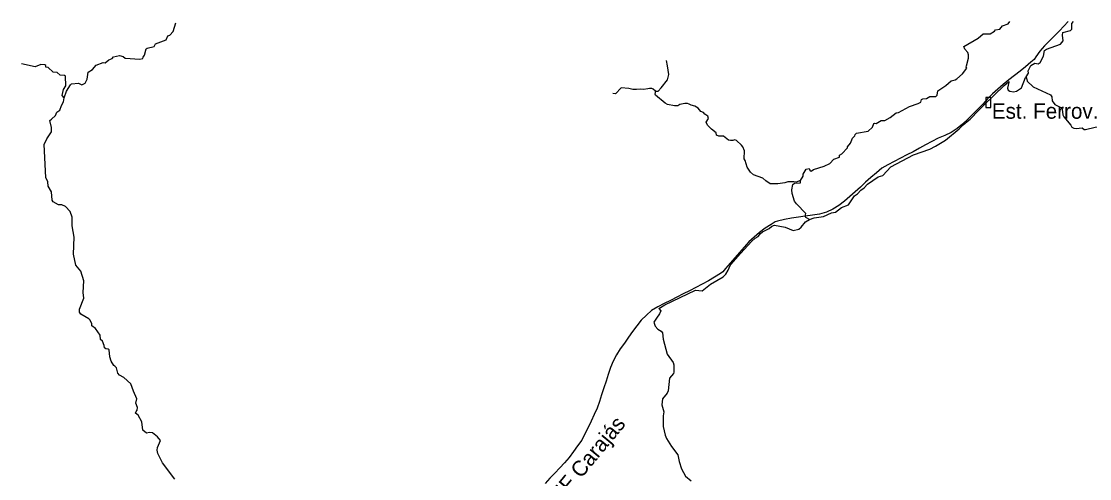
# Model space of a CAD drawing. Extents: x 332 to 501, y 9447 to 9559.
# Drawn here: x 333.47 to 359.78, y 9546.5 to 9557.76 of the extents above; entities that cross this region are included whole.
import ezdxf

# ---------------------------------------------------------------- set-up
doc = ezdxf.new("R2010")
doc.units = 0
for name, color, linetype in [('Level 19', 7, 'Continuous'), ('Level 22', 7, 'Continuous'), ('Level 28', 7, 'Continuous'), ('Level 31', 7, 'Continuous'), ('Level 4', 7, 'Continuous'), ('Level 5', 7, 'Continuous'), ('Level 6', 7, 'Continuous')]:
    doc.layers.add(name, color=color, linetype=linetype)

msp = doc.modelspace()

# ---------------------------------------------------------------- linework, layer by layer
at = {"layer": 'Level 22'}
for points in [[(359.2521, 9557.7639), (359.0383, 9557.5322)], [(359.0383, 9557.5322), (358.9143, 9557.4088)], [(358.7903, 9557.2853), (358.6662, 9557.1618)], [(358.9143, 9557.4088), (358.7903, 9557.2853)], [(358.5512, 9557.0309), (358.4517, 9556.887)], [(358.6662, 9557.1618), (358.5512, 9557.0309)], [(358.3324, 9556.761), (358.1983, 9556.6486)], [(358.4517, 9556.887), (358.4091, 9556.8253), (358.3324, 9556.761)], [(357.9247, 9556.4306), (357.7868, 9556.3229)], [(358.0642, 9556.5361), (357.9247, 9556.4306)], [(358.1983, 9556.6486), (358.0642, 9556.5361)], [(357.6506, 9556.213), (357.5185, 9556.0983)], [(357.7868, 9556.3229), (357.6506, 9556.213)], [(357.3864, 9555.9835), (357.2677, 9555.855)], [(357.5185, 9556.0983), (357.3864, 9555.9835)], [(357.1499, 9555.7256), (357.027, 9555.6011)], [(357.2677, 9555.855), (357.1499, 9555.7256)], [(356.7764, 9555.3567), (356.6512, 9555.2345)], [(356.9017, 9555.4789), (356.7764, 9555.3567)], [(357.027, 9555.6011), (356.9017, 9555.4789)], [(356.5153, 9555.1252), (356.3694, 9555.0291)], [(356.6512, 9555.2345), (356.5153, 9555.1252)], [(356.0504, 9554.885), (355.8943, 9554.8063)], [(356.2099, 9554.9571), (356.0504, 9554.885)], [(356.3694, 9555.0291), (356.2099, 9554.9571)], [(355.5868, 9554.6391), (355.4331, 9554.5554)], [(355.7405, 9554.7227), (355.5868, 9554.6391)], [(355.8943, 9554.8063), (355.7405, 9554.7227)], [(354.9676, 9554.3127), (354.8122, 9554.2321)], [(355.123, 9554.3933), (354.9676, 9554.3127)], [(355.2783, 9554.4739), (355.123, 9554.3933)], [(355.4331, 9554.5554), (355.2783, 9554.4739)], [(354.6602, 9554.1467), (354.5276, 9554.0325)], [(354.8122, 9554.2321), (354.6602, 9554.1467)], [(354.2635, 9553.8029), (354.134, 9553.6851)], [(354.3951, 9553.9181), (354.2635, 9553.8029)], [(354.5276, 9554.0325), (354.3951, 9553.9181)], [(354.0046, 9553.5673), (353.8752, 9553.4495)], [(354.134, 9553.6851), (354.0046, 9553.5673)], [(353.7388, 9553.3399), (353.6022, 9553.2305)], [(353.8752, 9553.4495), (353.7388, 9553.3399)], [(352.9554, 9552.9917), (352.7702, 9552.9656)], [(353.1285, 9553.0174), (352.9554, 9552.9917)], [(353.2968, 9553.0641), (353.1285, 9553.0174)], [(353.4553, 9553.1367), (353.2968, 9553.0641)], [(353.6022, 9553.2305), (353.4553, 9553.1367)], [(351.9402, 9552.7625), (351.7926, 9552.6684)], [(352.0947, 9552.8413), (352.0369, 9552.8241), (351.9402, 9552.7625)], [(352.263, 9552.8889), (352.0947, 9552.8413)], [(352.4361, 9552.9146), (352.263, 9552.8889)], [(352.6092, 9552.9403), (352.4361, 9552.9146)], [(352.7702, 9552.9656), (352.6092, 9552.9403)], [(351.6529, 9552.5638), (351.5201, 9552.4499)], [(351.7926, 9552.6684), (351.6529, 9552.5638)], [(351.2691, 9552.2072), (351.1551, 9552.0745)], [(351.3872, 9552.3359), (351.2691, 9552.2072)], [(351.5201, 9552.4499), (351.3872, 9552.3359)], [(351.0412, 9551.9417), (350.9272, 9551.8089)], [(351.1551, 9552.0745), (351.0412, 9551.9417)], [(350.8132, 9551.6761), (350.7446, 9551.5962), (350.6857, 9551.5589)], [(350.9272, 9551.8089), (350.8132, 9551.6761)], [(350.5378, 9551.4654), (350.3899, 9551.3719)], [(350.6857, 9551.5589), (350.5378, 9551.4654)], [(350.0787, 9551.2118), (349.9227, 9551.1325)], [(350.2347, 9551.2911), (350.0787, 9551.2118)], [(350.3899, 9551.3719), (350.2347, 9551.2911)], [(349.4548, 9550.8947), (349.2998, 9550.8133)], [(349.6108, 9550.974), (349.4548, 9550.8947)], [(349.7667, 9551.0532), (349.6108, 9550.974)], [(349.9227, 9551.1325), (349.7667, 9551.0532)], [(348.9922, 9550.6472), (348.8641, 9550.528)], [(349.145, 9550.7316), (348.9922, 9550.6472)], [(349.2998, 9550.8133), (349.145, 9550.7316)], [(348.7365, 9550.4083), (348.6302, 9550.2693)], [(348.8641, 9550.528), (348.7365, 9550.4083)], [(348.5238, 9550.1303), (348.4224, 9549.9878)], [(348.6302, 9550.2693), (348.5238, 9550.1303)], [(348.3226, 9549.8441), (348.2228, 9549.7003)], [(348.4224, 9549.9878), (348.3226, 9549.8441)], [(348.2228, 9549.7003), (348.1296, 9549.5525)], [(348.0493, 9549.397), (347.9791, 9549.2374)], [(348.1296, 9549.5525), (348.0493, 9549.397)], [(347.9266, 9549.0704), (347.874, 9548.9036)], [(347.9791, 9549.2374), (347.9266, 9549.0704)], [(347.874, 9548.9036), (347.8181, 9548.7377)], [(347.7622, 9548.5719), (347.7063, 9548.4061)], [(347.8181, 9548.7377), (347.7622, 9548.5719)], [(347.7063, 9548.4061), (347.6504, 9548.2402)], [(347.5796, 9548.0805), (347.5033, 9547.923)], [(347.6504, 9548.2402), (347.5796, 9548.0805)], [(347.4271, 9547.7654), (347.3509, 9547.6079)], [(347.5033, 9547.923), (347.4271, 9547.7654)], [(347.3509, 9547.6079), (347.2747, 9547.4504)], [(347.1708, 9547.3096), (347.0664, 9547.1692)], [(347.2747, 9547.4504), (347.1708, 9547.3096)], [(346.962, 9547.0287), (346.8506, 9546.8942)], [(347.0664, 9547.1692), (346.962, 9547.0287)], [(346.7301, 9546.7672), (346.6097, 9546.6403)], [(346.8506, 9546.8942), (346.7301, 9546.7672)], [(346.4892, 9546.5133), (346.3688, 9546.3863)], [(346.6097, 9546.6403), (346.4892, 9546.5133)]]:
    msp.add_lwpolyline(points, dxfattribs=at)
at = {"layer": 'Level 28'}
msp.add_lwpolyline([(357.2197, 9555.6407), (357.3447, 9555.6407), (357.3447, 9555.8907), (357.2197, 9555.8907)], close=True, dxfattribs=at)
at = {"layer": 'Level 4'}
for points in [[(334.5321, 9555.8808), (334.4776, 9555.9398), (334.5094, 9556.0852), (334.5684, 9556.176), (334.5593, 9556.4167), (334.5366, 9556.4349), (334.4277, 9556.4394), (334.355, 9556.503), (334.2597, 9556.5121), (334.1372, 9556.6302), (334.0782, 9556.6347), (334.0782, 9556.6802), (334.0509, 9556.6938), (333.9556, 9556.7029), (333.8149, 9556.6484), (333.4743, 9556.7219)], [(334.0796, 9553.9164), (334.0388, 9554.7339), (334.0974, 9554.8757), (334.22, 9555.0438), (334.22, 9555.1483), (334.1746, 9555.3254), (334.22, 9555.3526), (334.3108, 9555.448), (334.3516, 9555.5298), (334.4242, 9555.5797), (334.4605, 9555.6933), (334.5105, 9555.7796), (334.5321, 9555.8808)], [(334.722, 9552.9389), (334.6727, 9553.0825), (334.5638, 9553.2052), (334.4685, 9553.246), (334.3883, 9553.2488), (334.2612, 9553.3214), (334.2294, 9553.3623), (334.2203, 9553.5667), (334.1341, 9553.7029), (334.125, 9553.812), (334.0796, 9553.9164)], [(335.6395, 9549.6757), (335.6123, 9549.6939), (335.5533, 9549.6984), (335.5215, 9549.7257), (335.517, 9549.7847), (335.4716, 9549.8892), (335.4262, 9549.9301), (335.4171, 9550.0391), (335.2991, 9550.198), (335.2129, 9550.2662), (335.2129, 9550.3161), (335.1675, 9550.4069), (335.1357, 9550.4433), (334.9405, 9550.5523), (334.9087, 9550.6068), (334.9042, 9550.6749), (335.0086, 9550.9474), (334.995, 9551.0882), (335.0086, 9551.3789), (334.9405, 9551.613), (334.818, 9551.7629), (334.759, 9552.0354), (334.7726, 9552.4487), (334.7272, 9552.7303), (334.722, 9552.9389)], [(337.2496, 9546.4905), (336.9455, 9546.8901), (336.8366, 9547.1218), (336.8184, 9547.2035), (336.8275, 9547.2716), (336.9001, 9547.4442), (336.8275, 9547.5371), (336.7004, 9547.6324), (336.6323, 9547.6415), (336.5551, 9547.6279), (336.4689, 9547.696), (336.4371, 9547.905), (336.3471, 9548.0643), (336.2873, 9548.1139), (336.3009, 9548.1593), (336.3282, 9548.1865), (336.3327, 9548.2547), (336.2964, 9548.3591), (336.3146, 9548.4727), (336.2329, 9548.6543), (336.1738, 9548.8385), (336.0014, 9548.993), (335.8879, 9549.052), (335.8516, 9549.102), (335.8153, 9549.2291), (335.7789, 9549.2745), (335.7472, 9549.2882), (335.6849, 9549.3941), (335.6532, 9549.5077), (335.6395, 9549.6757)]]:
    msp.add_lwpolyline(points, dxfattribs=at)
at = {"layer": 'Level 5'}
for points in [[(334.5321, 9555.8808), (334.5876, 9556.043), (334.683, 9556.2019), (334.7102, 9556.2292), (334.8781, 9556.2383), (334.9644, 9556.1974), (335.0461, 9556.2383), (335.096, 9556.3382), (335.1187, 9556.5153), (335.2231, 9556.5789), (335.3139, 9556.6879), (335.4909, 9556.7515), (335.5401, 9556.7432), (335.6263, 9556.8159), (335.708, 9556.8477), (335.7444, 9556.8931), (335.8941, 9556.9204), (335.9804, 9556.8977), (336.0303, 9556.8613), (336.3935, 9556.8341), (336.4661, 9556.8477), (336.4706, 9556.884), (336.5069, 9556.9295), (336.5478, 9557.0839), (336.5705, 9557.1066), (336.743, 9557.1475), (336.7793, 9557.211), (337.038, 9557.3064), (337.0789, 9557.4063), (337.1333, 9557.4245), (337.215, 9557.5108), (337.2763, 9557.7273)], [(356.7493, 9556.6676), (356.7964, 9556.8559), (356.7964, 9556.9416), (356.7836, 9556.9972), (356.7065, 9557.0828), (356.6851, 9557.147), (357.0318, 9557.3483), (357.156, 9557.4597), (357.3315, 9557.4554), (357.4342, 9557.5196), (357.4642, 9557.5582), (357.5669, 9557.5753), (357.6312, 9557.6567), (357.7767, 9557.6995), (357.8101, 9557.7616)], [(358.2122, 9556.4015), (358.2717, 9556.4886), (358.2667, 9556.5476), (358.3307, 9556.6755), (358.429, 9556.7345), (358.5126, 9556.7148), (358.5569, 9556.7492), (358.6454, 9556.9066), (358.6651, 9557.0443), (358.7142, 9557.0836), (359.0585, 9557.2017), (359.1273, 9557.2846), (359.1076, 9557.4224), (359.1175, 9557.4913), (359.3043, 9557.5356), (359.3388, 9557.57), (359.3437, 9557.7127), (359.3777, 9557.7641)], [(355.0135, 9555.5139), (355.0685, 9555.5208), (355.3399, 9555.6651), (355.5592, 9555.7386), (355.6192, 9555.7729), (355.6406, 9555.8371), (355.6748, 9555.8542), (355.7604, 9555.8671), (355.8461, 9555.9141), (355.9916, 9555.9141), (356.0258, 9555.9441), (356.0387, 9556.0511), (356.2399, 9556.1838), (356.3683, 9556.3037), (356.4711, 9556.3208), (356.5053, 9556.3465), (356.6508, 9556.4749), (356.7579, 9556.6119)], [(356.7579, 9556.6119), (356.7365, 9556.6333), (356.7493, 9556.6676)], [(357.1753, 9555.7025), (357.6715, 9556.1889)], [(357.6715, 9556.1889), (357.778, 9556.278)], [(357.778, 9556.278), (357.7916, 9556.2827), (357.7928, 9556.2704), (357.7572, 9556.1167), (357.7768, 9556.0712), (357.8137, 9556.0454), (357.9072, 9556.0306), (357.9748, 9556.0442), (358.1026, 9556.1253), (358.1961, 9556.3823)], [(358.1961, 9556.3823), (358.2122, 9556.4015)], [(358.2122, 9556.4015), (358.2422, 9556.2956), (358.3848, 9556.148), (358.8126, 9555.9561), (358.847, 9555.902), (358.8568, 9555.8085), (358.9208, 9555.715), (359.0716, 9555.6432), (359.1011, 9555.6039), (359.1208, 9555.4612), (359.1405, 9555.4169), (359.3175, 9555.2053), (359.3372, 9555.161), (359.3913, 9555.1315), (359.4503, 9555.1266), (359.5929, 9555.1413), (359.6421, 9555.102), (359.6765, 9555.102), (359.9174, 9555.161), (360.0945, 9555.166), (360.1781, 9555.1069), (360.2027, 9555.0577), (360.2568, 9555.0331)], [(352.6618, 9553.8449), (352.5544, 9553.8035), (352.4945, 9553.8164), (352.3447, 9553.8121), (352.2762, 9553.7864), (352.1007, 9553.7607), (351.9123, 9553.765), (351.8096, 9553.8335), (351.7282, 9553.9021), (351.5014, 9553.9834), (351.4243, 9554.052), (351.343, 9554.1762), (351.2959, 9554.339), (351.2745, 9554.3818), (351.283, 9554.5745), (351.2402, 9554.6731), (351.206, 9554.7159), (351.0861, 9554.8273), (351.0433, 9554.8444), (350.9919, 9554.8316), (350.9363, 9554.8273), (350.8849, 9554.8358), (350.7651, 9554.9386), (350.6495, 9554.9344), (350.5895, 9554.9643), (350.5853, 9555.02), (350.4654, 9555.1057), (350.3712, 9555.2085), (350.3327, 9555.2813), (350.3969, 9555.3713), (350.3755, 9555.4296), (350.307, 9555.481), (350.2728, 9555.5238), (350.2043, 9555.541), (350.1401, 9555.6267), (350.0587, 9555.6781), (349.9688, 9555.6995), (349.9217, 9555.7252), (349.8746, 9555.738), (349.8147, 9555.738), (349.6863, 9555.7166), (349.6392, 9555.6866), (349.6221, 9555.6882), (349.5595, 9555.6866), (349.3883, 9555.7209), (349.3241, 9555.7466), (349.0886, 9555.9436), (349.0801, 9555.9736), (349.0929, 9556.0122), (349.0929, 9556.0464), (349.033, 9556.0978), (348.9945, 9556.115), (348.9431, 9556.115), (348.896, 9556.1021), (348.7933, 9556.0893), (348.729, 9556.0978), (348.6177, 9556.085), (348.5279, 9556.085), (348.4294, 9556.115), (348.241, 9556.1235), (348.1041, 9555.9822), (348.0356, 9555.9865)], [(357.051, 9555.5765), (357.1753, 9555.7025)], [(352.6619, 9553.8449), (352.7244, 9553.955), (352.7244, 9553.9996), (352.8001, 9554.1246), (352.8715, 9554.1424), (352.8893, 9554.0978), (352.9205, 9554.0755), (352.9785, 9554.1156), (353.246, 9554.2004), (353.3798, 9554.2673), (353.4765, 9554.3699), (353.6192, 9554.419), (353.6192, 9554.4725), (353.6788, 9554.5061), (353.8171, 9554.6493), (353.8154, 9554.6721), (353.891, 9554.7649), (353.9425, 9554.8885), (354.0009, 9554.9435), (354.0078, 9554.9779), (354.0422, 9555.0122), (354.3239, 9555.0569), (354.4304, 9555.1565), (354.4647, 9555.2458), (354.4888, 9555.2596), (354.5232, 9555.2493), (354.6468, 9555.3214), (354.7396, 9555.3249), (354.8667, 9555.397), (355.0135, 9555.5139)], [(356.8023, 9555.3302), (356.8347, 9555.3571)], [(356.8347, 9555.3571), (357.051, 9555.5765)], [(352.8846, 9552.8893), (352.992, 9552.9296), (353.2267, 9552.9631), (353.4223, 9553.047), (353.5173, 9553.0638), (353.6682, 9553.1812), (353.8414, 9553.2427), (353.9923, 9553.4646), (354.0649, 9553.5205), (354.1432, 9553.6099), (354.227, 9553.6659), (354.3108, 9553.7553), (354.5679, 9553.9343), (354.6852, 9553.9678), (354.8864, 9554.1859), (355.4432, 9554.4736), (355.84, 9554.619), (355.9853, 9554.6917), (356.2256, 9554.8427), (356.5665, 9555.1167), (356.6675, 9555.2178)], [(356.6675, 9555.2178), (356.8023, 9555.3302)], [(352.7702, 9552.9656), (352.7928, 9553.0305), (352.5594, 9553.2694), (352.5148, 9553.3363), (352.4568, 9553.5237), (352.4435, 9553.6174), (352.4702, 9553.7512), (352.5148, 9553.7825), (352.6575, 9553.7869), (352.6619, 9553.8449)], [(351.6731, 9552.5401), (351.726, 9552.5824), (351.8881, 9552.6607), (351.9495, 9552.7221), (352.0166, 9552.7445), (352.2792, 9552.6942), (352.4804, 9552.616), (352.6145, 9552.6439), (352.6728, 9552.6988)], [(352.6728, 9552.6988), (352.7852, 9552.8289), (352.8846, 9552.8893)], [(352.7886, 9552.9345), (352.7702, 9552.9656)], [(352.8846, 9552.8893), (352.7886, 9552.9345)], [(351.544, 9552.4219), (351.6142, 9552.4651), (351.6731, 9552.5401)], [(351.1838, 9552.0501), (351.4634, 9552.3533), (351.544, 9552.4219)], [(351.0677, 9551.9191), (351.1838, 9552.0501)], [(349.3152, 9550.7843), (350.0719, 9551.1462), (350.2395, 9551.1295), (350.4407, 9551.2915), (350.7536, 9551.4759), (350.8207, 9551.543), (350.8822, 9551.638), (350.9269, 9551.7554), (350.9533, 9551.7861)], [(350.9533, 9551.7861), (351.0677, 9551.9191)], [(349.1693, 9550.6929), (349.3152, 9550.7843)], [(349.1693, 9550.6929), (349.2202, 9550.6341), (349.1844, 9550.5665)], [(349.0623, 9550.3821), (349.0518, 9550.356), (349.0792, 9550.2619), (349.1497, 9550.1836), (349.2319, 9550.1366), (349.2633, 9550.0935), (349.275, 9549.9368), (349.3768, 9549.5724), (349.5217, 9549.3648), (349.5413, 9549.3099), (349.5413, 9549.1279), (349.5295, 9549.0926), (349.4316, 9548.9751), (349.4003, 9548.6656), (349.3768, 9548.6107), (349.2594, 9548.4697), (349.2437, 9548.3247), (349.2946, 9548.1523), (349.2789, 9548.0505), (349.275, 9547.788), (349.3298, 9547.5743), (349.3612, 9547.492), (349.4825, 9547.2961), (349.6352, 9547.0924), (349.6705, 9546.9239), (349.7292, 9546.7476), (349.8236, 9546.5651), (349.9633, 9546.4516)], [(349.1126, 9550.4532), (349.0623, 9550.3821)], [(349.1844, 9550.5665), (349.1126, 9550.4532)]]:
    msp.add_lwpolyline(points, dxfattribs=at)
at = {"layer": 'Level 6'}
msp.add_lwpolyline([(349.0929, 9556.0464), (349.1511, 9556.0443), (349.2306, 9556.1313), (349.3819, 9556.328), (349.3819, 9556.328), (349.4159, 9556.4566), (349.3819, 9556.6722), (349.363, 9556.8008)], dxfattribs=at)

# ---------------------------------------------------------------- texts
at = {"layer": 'Level 19'}
msp.add_text('Est. Ferrov. Presa de Porco', height=0.38, dxfattribs=at).set_placement((357.3703, 9555.3665))
at = {"layer": 'Level 31'}
msp.add_text('EF Carajás', height=0.38, rotation=50.38046, dxfattribs=at).set_placement((346.7521, 9545.8833))

doc.saveas('drawing.dxf')
